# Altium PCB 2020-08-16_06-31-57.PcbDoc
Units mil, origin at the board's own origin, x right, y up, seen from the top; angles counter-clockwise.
Board outline 2200 x 1600 mil, 4 copper layers (Top Layer, MidLayer1, MidLayer2, Bottom Layer); 13 components, 5 nets, 26 pads, 25 vias.
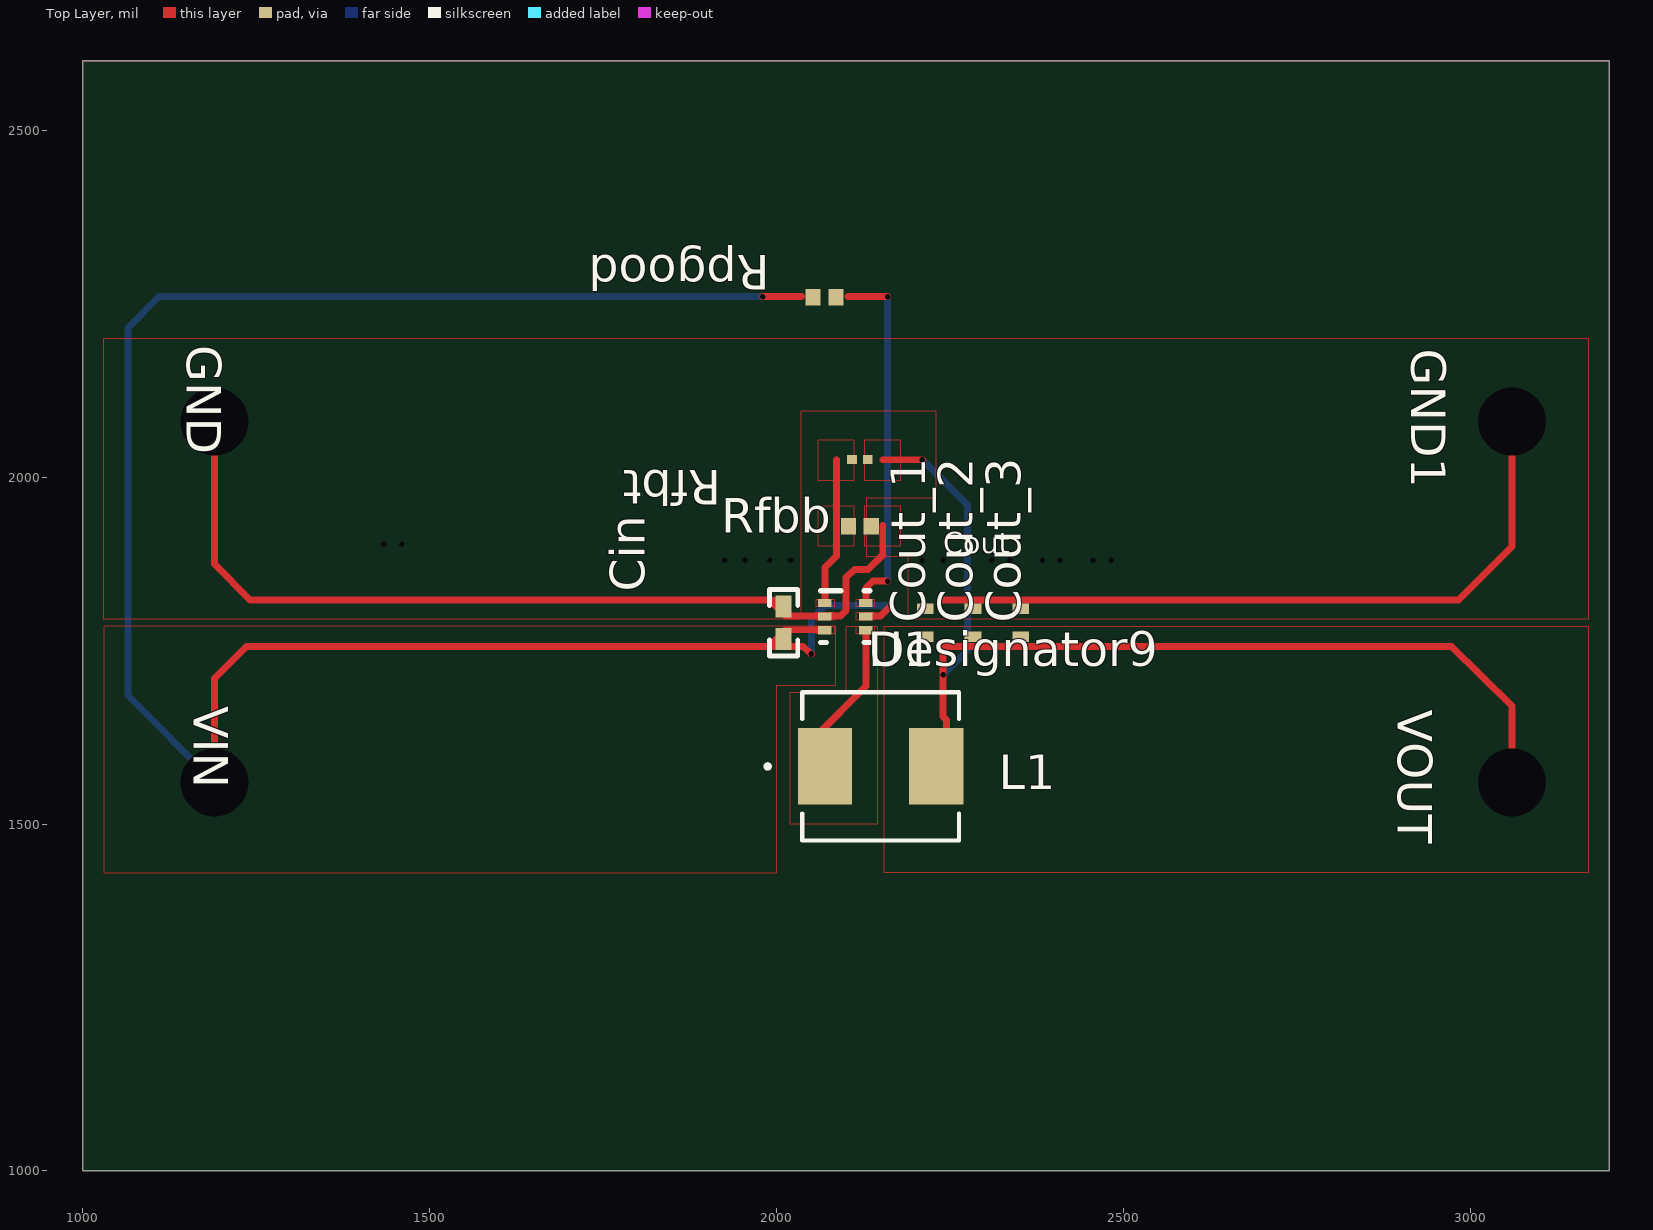
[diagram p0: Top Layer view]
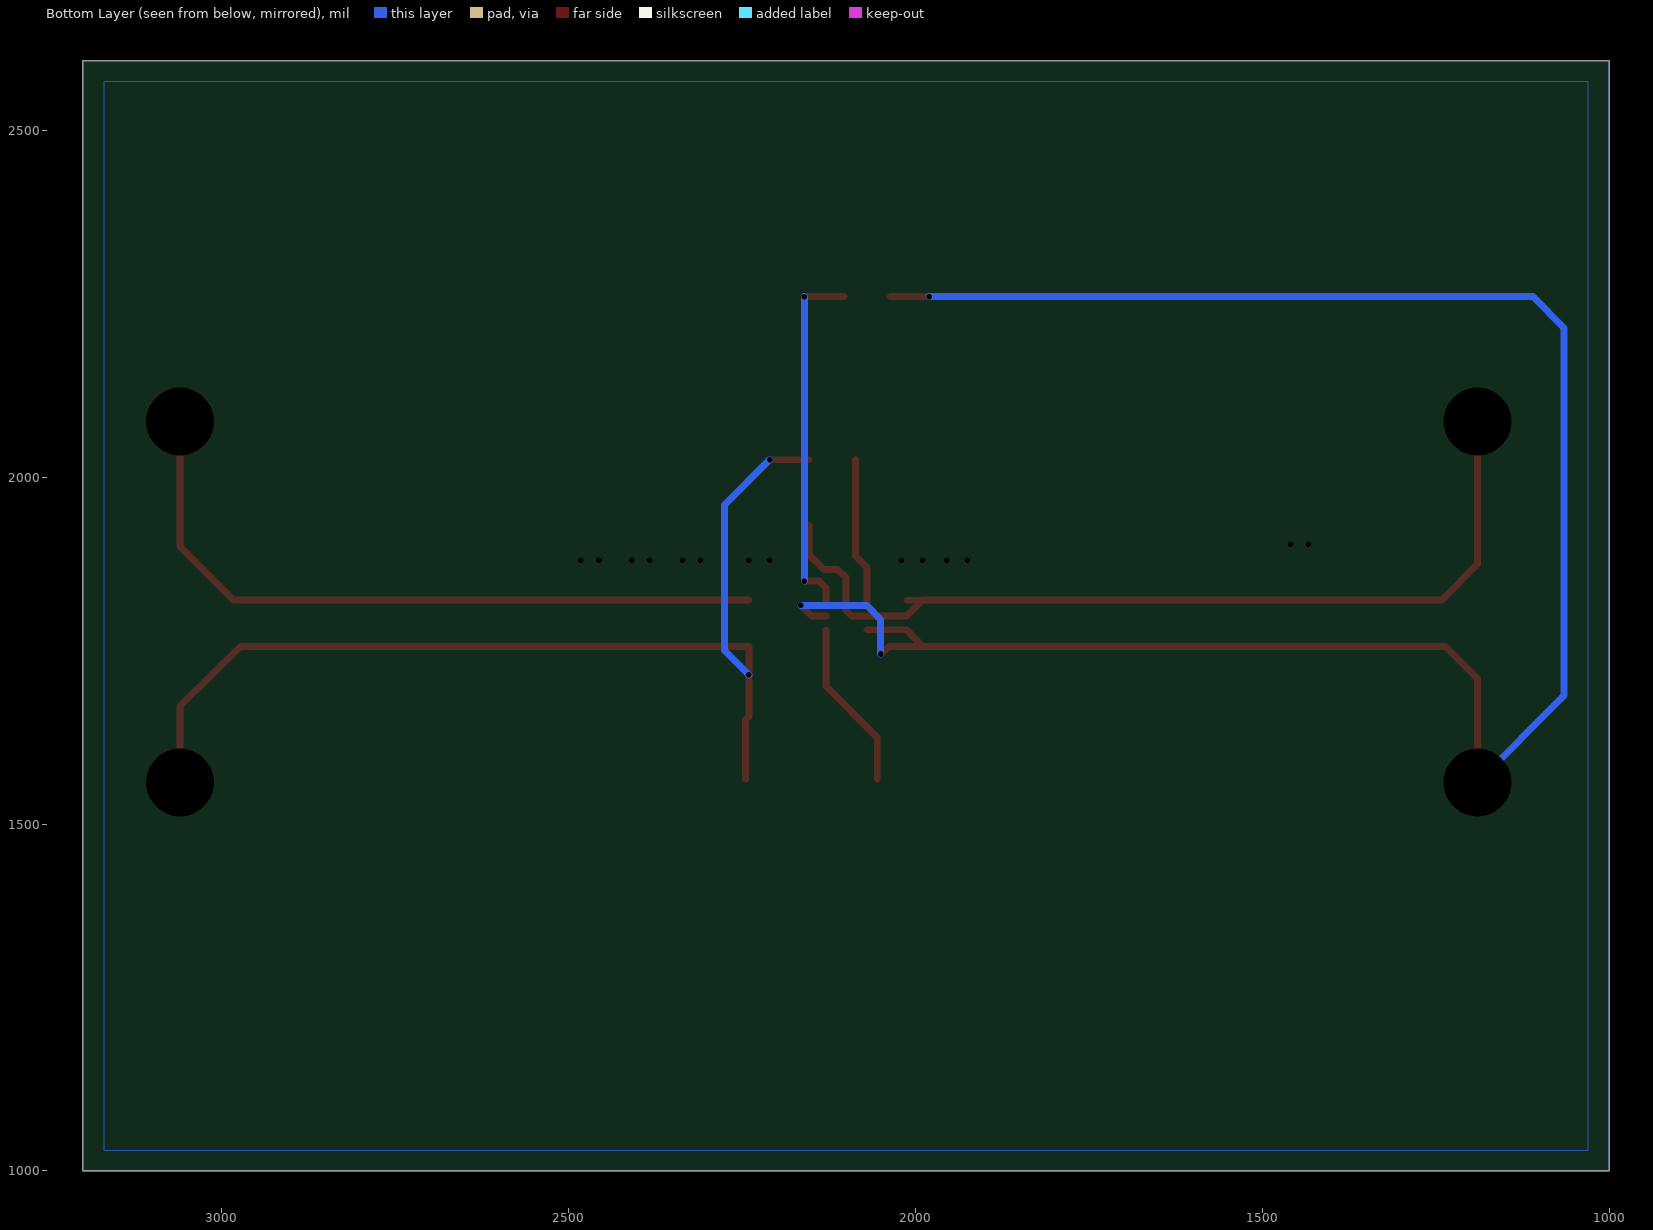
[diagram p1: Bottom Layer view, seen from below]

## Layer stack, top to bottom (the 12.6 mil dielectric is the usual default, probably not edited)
Top Layer: signal copper 1.4
Dielectric: core 12.6, FR-4, Dk 4.8
MidLayer1: signal copper 1.4
Dielectric: prepreg 12.6, FR-4, Dk 4.8
MidLayer2: signal copper 1.4
Dielectric: core 12.6, FR-4, Dk 4.8
Bottom Layer: signal copper 1.4

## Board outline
1000,1000 3200,1000 3200,2600 1000,2600

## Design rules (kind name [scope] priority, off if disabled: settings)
PlaneConnect [All] p0: scope1count=1 scope1_0_kind=Board scope1_0_value=Board scope2count=1 scope2_0_kind=Board scope2_0_value=Board commentlength=0 planeconnectstyle=Direct reliefexpansion=20 reliefentries=4 reliefconductorwidth=10 reliefairgap=10
PlaneConnect [All] p1: planeconnectstyle=Direct reliefexpansion=20 reliefentries=4 reliefconductorwidth=10 reliefairgap=10
PolygonConnect [All] p0: scope1count=1 scope1_0_kind=Board scope1_0_value=Board scope2count=1 scope2_0_kind=Board scope2_0_value=Board commentlength=0 connectstyle=Direct reliefconductorwidth=10 reliefentries=4 polygonreliefangle="90 Angle"
PolygonConnect [All] p1: connectstyle=Direct reliefconductorwidth=10 reliefentries=4 polygonreliefangle="90 Angle"

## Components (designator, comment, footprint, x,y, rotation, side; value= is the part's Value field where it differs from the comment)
Cin "" 0402_065 2010,1790 r90 top
Cout_1 "" 0402_070 2214,1790 r90 top
Cout_2 "" 0402_070 2283,1790 r90 top
Cout_3 "" 0402_070 2352,1790 r90 top
GND "" TP-1502 1189,2079 r270 top
GND1 "" TP-1502 3059,2079 r270 top
L1 "" IHLP-2020CZ 2150,1583 r0 top
Rfbb "" 0402 2120,1929 r0 top
Rfbt "" 0201 2120,2025 r180 top
Rpgood "" 0402 2069,2259 r180 top
U1 "" DRL0006A 2099,1799 r0 top
VIN "" TP-1502 1189,1559 r270 top
VOUT "" TP-1502 3059,1559 r270 top

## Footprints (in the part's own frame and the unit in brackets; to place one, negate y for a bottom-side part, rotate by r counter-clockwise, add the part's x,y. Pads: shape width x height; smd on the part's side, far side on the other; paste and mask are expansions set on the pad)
0201 [mil]
  rect 14x13 smd: 1(-11.5,0) 2(11.5,0)
0402 [mil]
  rect 22x24 smd: 1(-16.5,0) 2(16.5,0)
0402_065 [mm]
  rect 0.8x0.6 smd: 1(-0.6,0) 2(0.6,0)
  silkscreen extent -1.22,-0.52 1.22,0.52
0402_070 [mil]
  rect 15x24 smd: 1(-20,0) 2(20,0)
DRL0006A [mm]
  rect 0.5x0.3 smd: 1(-0.75,0.5) 2(-0.75,0) 3(-0.75,-0.5) 4(0.75,-0.5) 5(0.75,0) 6(0.75,0.5)
  silkscreen extent -0.9,-0.95 0.9,0.95
IHLP-2020CZ [mil]
  rect 78x110 smd: 1(-80,0) 2(80,0)
  silkscreen extent -166,-107 113,107
TP-1502 [mil]
  round 65 / inner round 0 / far side round 65 hole 32: 1(0,0)

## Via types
v1: diameter 0, hole 8, Top Layer to Bottom Layer, 21 vias
v2: diameter 0, hole 98, Top Layer to Bottom Layer, 4 vias

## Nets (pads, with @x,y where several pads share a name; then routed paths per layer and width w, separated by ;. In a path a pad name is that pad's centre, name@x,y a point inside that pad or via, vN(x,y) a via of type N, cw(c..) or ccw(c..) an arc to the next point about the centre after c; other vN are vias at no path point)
0: Cin.2 Cout_1.2 Cout_2.2 Cout_3.2 GND1.1 GND.1 Rfbb.2 U1.2 | length 2382.2
  Top Layer w10: v2(1190,2080) 1190,1875 1241,1823 1990,1823 2013,1800 2070,1800 2092,1800 2100,1808 2100,1855 2112,1867 2132,1867 2153,1888 2153,1930 ; 1967,1822.5 Cin.2@2012,1822.5 ; 2240,1823 2983,1823 3060,1900 v2(3060,2080)
  other v1: 1925,1880 1955,1880 1990,1880 2020,1880 2210,1880 2240,1880 2310,1880 2336,1880 2383,1880 2409,1880 2456,1880 2482,1880 1434,1903 1460,1903
1: Rfbb.1 Rfbt.2 U1.1 | length 212.6
  Top Layer w10: U1.1@2070,1819 2070,1870 2086,1886 2086,1930 2086,2025
2: Cin.1 L1.1 Rpgood.2 U1.3 U1.4 U1.5 VIN.1 | length 3326.1
  Top Layer w10: v2(1190,1560) 1190,1710 1236,1756 1990,1756 ; 1967,1755.5 Cin.1@2012,1755.5 ; v1(1980,2260) 2036,2260 ; v1(2050,1745) 2038,1756 1990,1756 ; L1.1@2055,1565 2055,1625 2129,1699 U1.4@2129,1780 ; U1.3@2070,1780 2013,1780 1990,1756 ; U1.5@2129,1800 2150,1800 v1(2165,1815)
  Bottom Layer w10: v2(1190,1560) 1065,1685 1065,2215 1110,2260 v1(1980,2260) ; v1(2050,1745) 2050,1795 2070,1815 v1(2165,1815)
5: Cout_1.1 Cout_2.1 Cout_3.1 L1.2 Rfbt.1 VOUT.1 | length 1567.8
  Top Layer w10: 2153,2025 v1(2210,2025) ; L1.2@2244,1565 2245,1565 2245,1650 2240,1655 v1(2240,1715) 2240,1756 2973,1756 3060,1670 v2(3060,1560)
  Bottom Layer w10: v1(2210,2025) 2275,1960 2275,1750 v1(2240,1715)
6: Rpgood.1 U1.6 | length 523.1
  Top Layer w10: 2103,2260 v1(2160,2260) ; U1.6@2129,1819 2129,1840 2139,1850 v1(2160,1850)
  Bottom Layer w10: v1(2160,1850) v1(2160,2260)

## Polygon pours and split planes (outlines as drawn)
6 on Top Layer " " (solid, pour order 0): 2115,1813 2115,1824 2141,1824 2141,1813
2 on Top Layer " " (solid, pour order 1): 2115,1794 2115,1805 2141,1805 2141,1794
2 on Top Layer " " (solid, pour order 2): 2115,1774 2115,1785 2141,1785 2141,1774
1 on Top Layer " " (solid, pour order 3): 2057,1813 2057,1824 2083,1824 2083,1813
2 on Top Layer " " (solid, pour order 4): 2057,1774 2057,1785 2083,1785 2083,1774
1 on Top Layer " " (solid, pour order 5): 2060,1900 2060,1959 2111,1959 2111,1900
1 on Top Layer " " (solid, pour order 6): 2060,1995 2060,2054 2111,2054 2111,1995
5 on Top Layer " " (solid, pour order 7): 2127,1995 2127,2054 2178,2054 2178,1995
2 on Top Layer " " (solid, pour order 8): 2145,1785 2145,1500 2020,1500 2020,1690 2100,1690 2100,1785
5 on Top Layer " " (solid, pour order 9): 3170,1785 3170,1430 2155,1430 2155,1785
2 on Top Layer " " (solid, pour order 10): 2000,1430 2000,1700 2085,1700 2085,1785 1030,1785 1030,1430
0 on Top Layer " " (solid, pour order 11): 2057,1794 2057,1805 2083,1805 2083,1794
0 on Top Layer " " (solid, pour order 12): 2127,1900 2127,1959 2178,1959 2178,1900
0 on Top Layer " " (solid, pour order 14): 2130,1970 2230,1970 2230,2095 2035,2095 2035,1795 1030,1795 1030,2200 3170,2200 3170,1795 2190,1795 2190,1885 2130,1885
0 on Bottom Layer " " (solid, pour order 13): 1030,2570 3170,2570 3170,1030 1030,1030

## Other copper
Multi-Layer:
  the board outline again, w1

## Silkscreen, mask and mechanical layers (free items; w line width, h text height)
Top Overlay:
  text "Cout" at 2240,1890 h30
